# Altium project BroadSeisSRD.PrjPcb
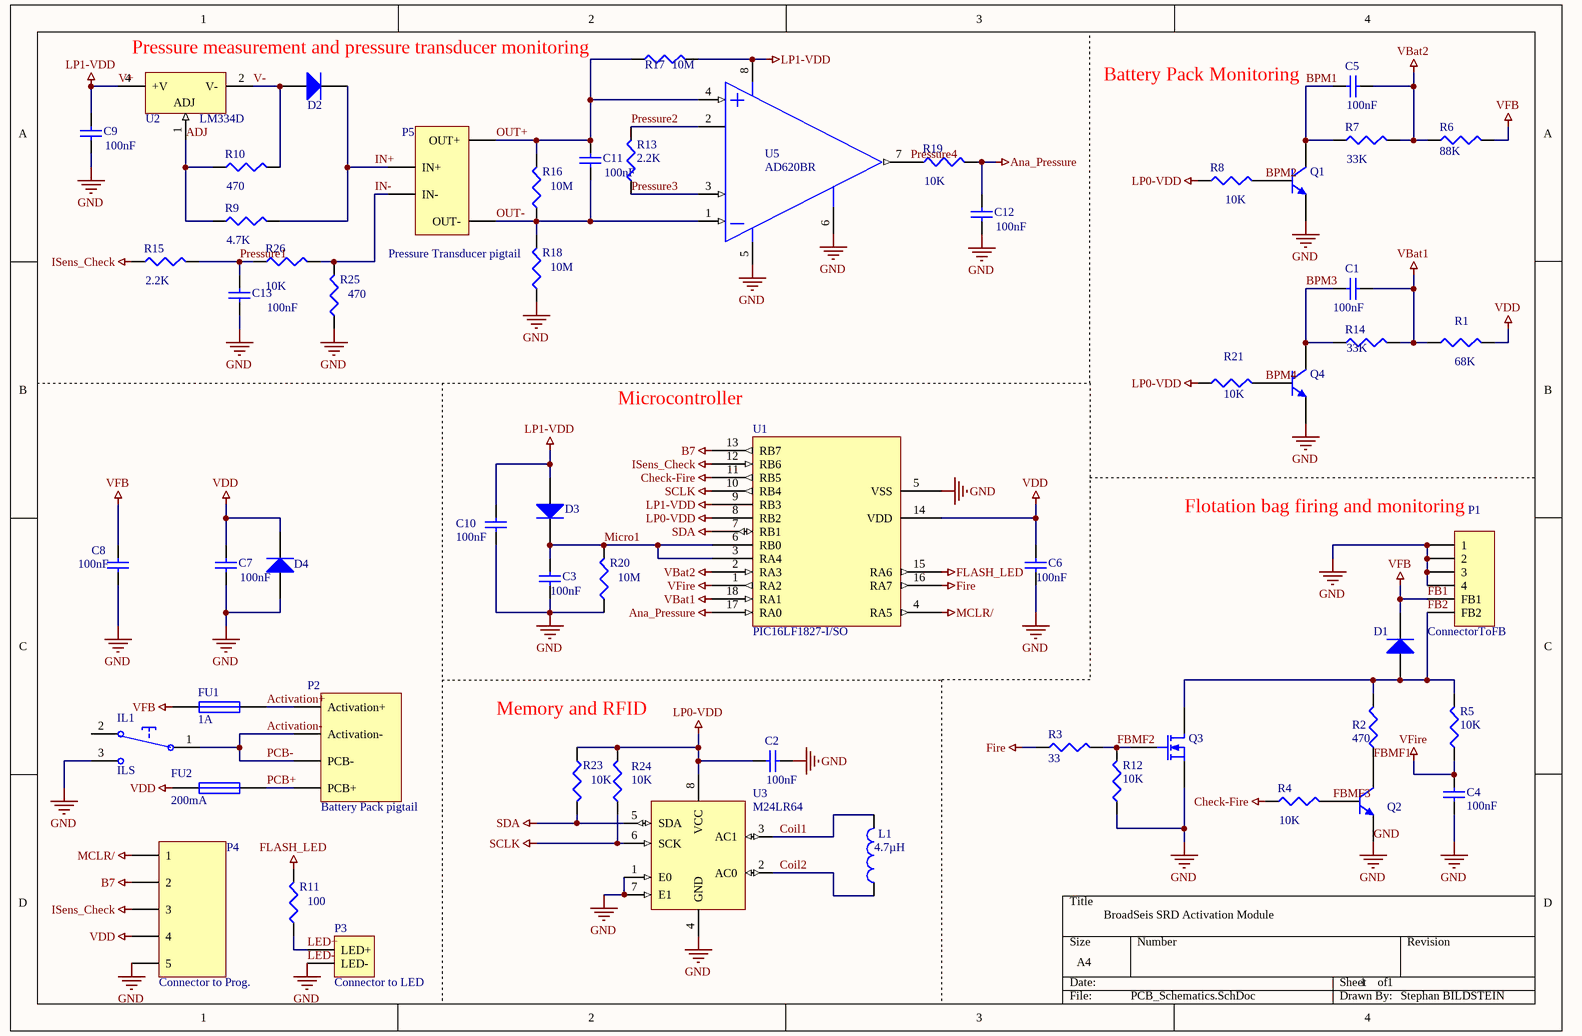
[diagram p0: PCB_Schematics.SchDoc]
1 sheet, 59 parts. Net scope: global (net labels, ports and power ports of the same name join across sheets).
Board file: PCB_Rooting.PcbDoc

## Sheet PCB_Schematics.SchDoc
size A4; SheetNumber: 1; SheetTotal: 1; PageSetup: Record=PageOptions|CenterHorizontal=True|CenterVertical=True|PrintScale=1.00|XCorrection=1.00|YCorrection=1.00|PrintKind=1|BorderSize=5000000|LeftOffset=0|BottomOffset=0|Orientation=2|PaperLength=1000|PaperWidth=1000|Scale=100|PaperSource=7|PrintQuality=1200|MediaType=1|DitherType=10|PaperKind=A4|PrintScaleMode=1

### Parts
C1  value 100nF  [1608[0603]]
C2  value 100nF  [1608[0603]]
C3  value 100nF  [1608[0603]]
C4  value 100nF  [1608[0603]]
C5  value 100nF  [1608[0603]]
C6  value 100nF  [1608[0603]]
C7  value 100nF  [1608[0603]]
C8  value 100nF  [1608[0603]]
C9  value 100nF  [1608[0603]]
C10  value 100nF  [1608[0603]]
C11  value 100nF  [1608[0603]]
C12  value 100nF  [1608[0603]]
C13  value 100nF  [1608[0603]]
D1  (no value)  [DiodeRS1D(recommendedfootprint)]
D2  (no value)  [SOT-23_M]
D3  (no value)  [SOT-23_M]
D4  (no value)  [DiodeRS1D(recommendedfootprint)]
FU1  1A  [FU(recommendedfootprint)]
FU2  200mA  [FU(recommendedfootprint)]
IL1  ILS  [ILS]
L1  value 4.7µH  [INDC4532]
P1  ConnectorToFB  [HIROSE DF3DZ 6P-2V]
P2  Battery Pack pigtail  [HDR1X4]
P3  Connector to LED  [HDR1X2]
P4  Connector to Prog.  [HDR1X5]
P5  Pressure Transducer pigtail  [HDR1X4]
Q1  (no value)  [transistor_SOT-23(recommendedfootprint)]
Q2  (no value)  [transistor_SOT-23(recommendedfootprint)]
Q3  (no value)  [transistor_SOT-23(recommendedfootprint)]
Q4  (no value)  [transistor_SOT-23(recommendedfootprint)]
R1  value 68K  [J1-0603]
R2  value 470  [J1-0603]
R3  value 33  [J1-0603]
R4  value 10K  [J1-0603]
R5  value 10K  [J1-0603]
R6  value 88K  [J1-0603]
R7  value 33K  [J1-0603]
R8  value 10K  [J1-0603]
R9  value 4.7K  [J1-0603]
R10  value 470  [J1-0603]
R11  value 100  [J1-0603]
R12  value 10K  [J1-0603]
R13  value 2.2K  [J1-0603]
R14  value 33K  [J1-0603]
R15  value 2.2K  [J1-0603]
R16  value 10M  [J1-0603]
R17  value 10M  [J1-0603]
R18  value 10M  [1608[0603]]
R19  value 10K  [J1-0603]
R20  value 10M  [J1-0603]
R21  value 10K  [J1-0603]
R23  value 10K  [J1-0603]
R24  value 10K  [J1-0603]
R25  value 470  [J1-0603]
R26  value 10K  [J1-0603]
U1  PIC16LF1827-I/SO  [SOIC-SO18_L]
U2  LM334D  [SO8_N]
U3  M24LR64  [SO8N_N]
U5  AD620BR  [R-8D_N]

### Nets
Ana_Pressure: C12.2 R19.2 U1.17(RA0)
B7: P4.2 U1.13(RB7)
Check-Fire: R4.1 U1.11(RB5)
FB1: C8.2 D1.2(K) FU1.2 P1.6(FB1) R6.2  [also labelled VFB]
Fire: R3.1 U1.16(RA7)
FLASH_LED: R11.2 U1.15(RA6)
GND: C2.1 C3.1 C4.1 C6.1 C7.1 C8.1 C9.1 C10.1 C12.1 C13.1 D4.1(A) IL1.3 P1.1 P1.2 P1.3 P1.4 P3.2(LED-) P4.5 Q1.2(E) Q2.2(E) Q3.2(S) Q4.2(E) R12.1 R18.1 R20.1 R25.1 U1.5(VSS) U3.1(E0) U3.4(GND) U3.7(E1) U5.5(V-) U5.6(RG)  [also labelled LED-]
ISens_Check: P4.3 R15.1 U1.12(RB6)
LP0-VDD: C2.2 R8.1 R21.1 R23.1 R24.2 U1.8(RB2) U3.8(VCC)
MCLR/: P4.1 U1.4(RA5)
SCLK: R24.1 U1.10(RB4) U3.6(SCK)
SDA: R23.2 U1.7(RB1) U3.5(SDA)
V+: C9.2 C10.2 D3.1(A) R17.2 U1.9(RB3) U2.4(+V) U5.8(V+)  [also labelled LP1-VDD]
VBat1: C1.2 R1.1 R14.2 U1.18(RA1)
VBat2: C5.2 R6.1 R7.2 U1.2(RA3)
VDD: C6.2 C7.2 D4.2(K) FU2.1 P4.4 R1.2 U1.14(VDD)
VFire: C4.2 R5.1 U1.1(RA2)
Activation+: FU1.1 P2.1(Activation+)
Activation-: IL1.1 P2.2(Activation-) P2.3(PCB-)  [also labelled PCB-]
ADJ: R9.1 R10.1 U2.1(ADJ)
BPM1: C5.1 Q1.3(C) R7.1
BPM2: Q1.1(B) R8.2
BPM3: C1.1 Q4.3(C) R14.1
BPM4: Q4.1(B) R21.2
Coil1: L1.2 U3.3(AC1)
Coil2: L1.1 U3.2(AC0)
FB2: D1.1(A) P1.5(FB2) Q3.3(D) R2.2 R5.2
FBMF1: Q2.3(C) R2.1
FBMF2: Q3.1(G) R3.2 R12.2
FBMF3: Q2.1(B) R4.2
IN+: D2.3(K) P5.1(IN+) R9.2
IN-: P5.3(IN-) R25.2 R26.2
LED+: P3.1(LED+) R11.1
Micro1: C3.2 D3.3(K) R20.2 U1.3(RA4) U1.6(RB0)
OUT+: C11.2 P5.2(OUT+) R16.2 R17.1 U5.4(+IN)
OUT-: C11.1 P5.4(OUT-) R16.1 R18.2 U5.1(-IN)
PCB+: FU2.2 P2.4(PCB+)
Pressure1: C13.2 R15.2 R26.1
Pressure2: R13.2 U5.2(RG)
Pressure3: R13.1 U5.3(REF)
Pressure4: R19.1 U5.7(OUT)
V-: D2.1(A) R10.2 U2.2(V-)

Not connected (* = marked no-connect by the designer): IL1 2

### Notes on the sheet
- (near R17) Pressure measurement and pressure transducer monitoring
- (near C5) Battery Pack Monitoring
- (near U1) Microcontroller
- (near P1) Flotation bag firing and monitoring
- Memory and RFID
- BroadSeis SRD Activation Module
- 1
- Stephan BILDSTEIN

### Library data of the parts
C1-C13 = Cap Semi: Capacitor (Semiconductor SIM Model)
D1 D4 = Diode: Default Diode
D2 D3 = Diode BAS16: Silicon Switching Diode for High-Speed Switching; Note: Pin 2 is not connected and not drawn.
FU1 FU2 = Fuse 1: Fuse
IL1 = ILS: SPDT Subminiature Toggle Switch, Right Angle Mounting, Vertical Actuation
L1 = Inductor: Code_IEC: 1005
P1 = ConnectorToFB: Header, 6-Pin
P2 = Battery Pack pigtail: Header, 4-Pin
P3 = Connector to LED: Header, 2-Pin
P4 = Connector to Prog.: Header, 5-Pin
P5 = Pressure Transducer pigtail: Header, 4-Pin
Q1 Q2 Q4 = NPN: NPN Bipolar Transistor
Q3 = MOSFET-IRLML: N-Channel MOSFET
R1-R21 R23-R26 = Res3: Resistor
U1 = PIC16LF1827-I/SO: EPROM-Based 8-Bit CMOS Microcontroller, 25 Bytes RAM, 4 MHz, 18-Pin SOIC, 3.0 to 5.5V Supply Range, Extended Temperature; Note: Verify oscillator characteristics if changing from this device to another.; Note: 20mA source and 25mA sink per I/O.
U2 = LM334D: Three Terminal Adjustable Current Source
U3 = M24LR64: 32 Kbit Serial I²C Bus EEPROM
U5 = AD620BR: Low-Cost, Low-Power Instrumentation Amplifier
